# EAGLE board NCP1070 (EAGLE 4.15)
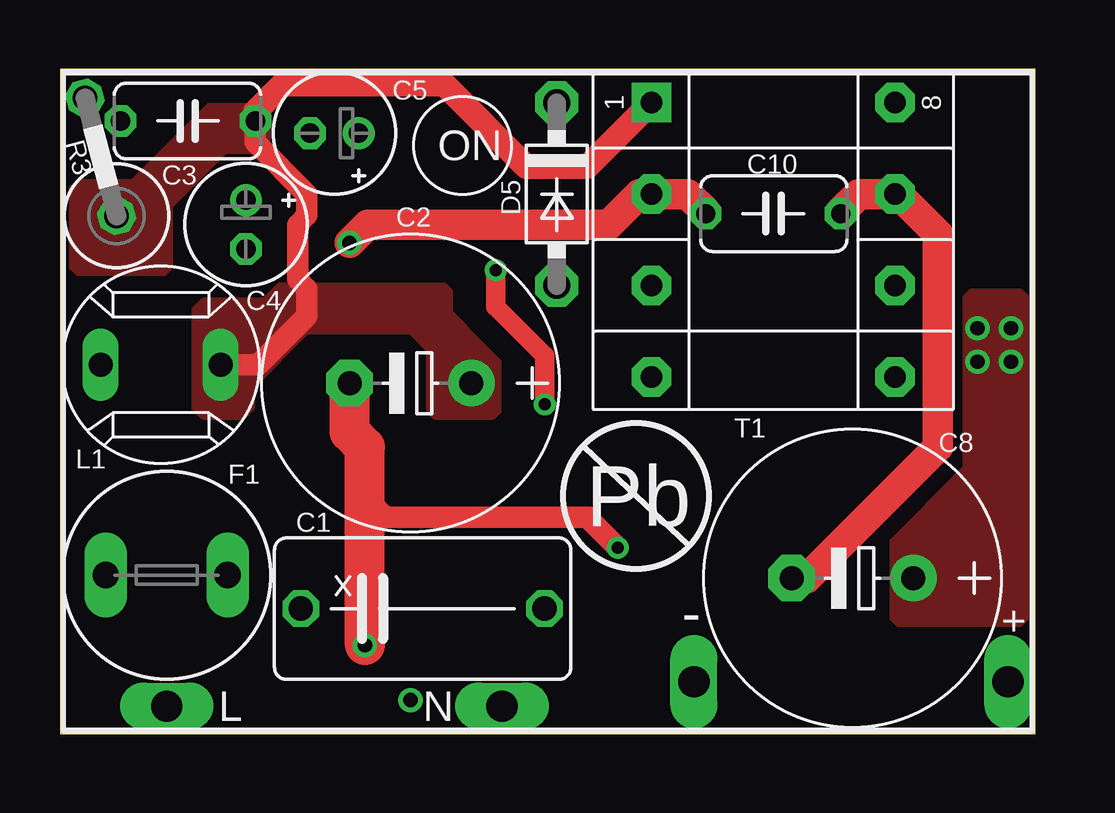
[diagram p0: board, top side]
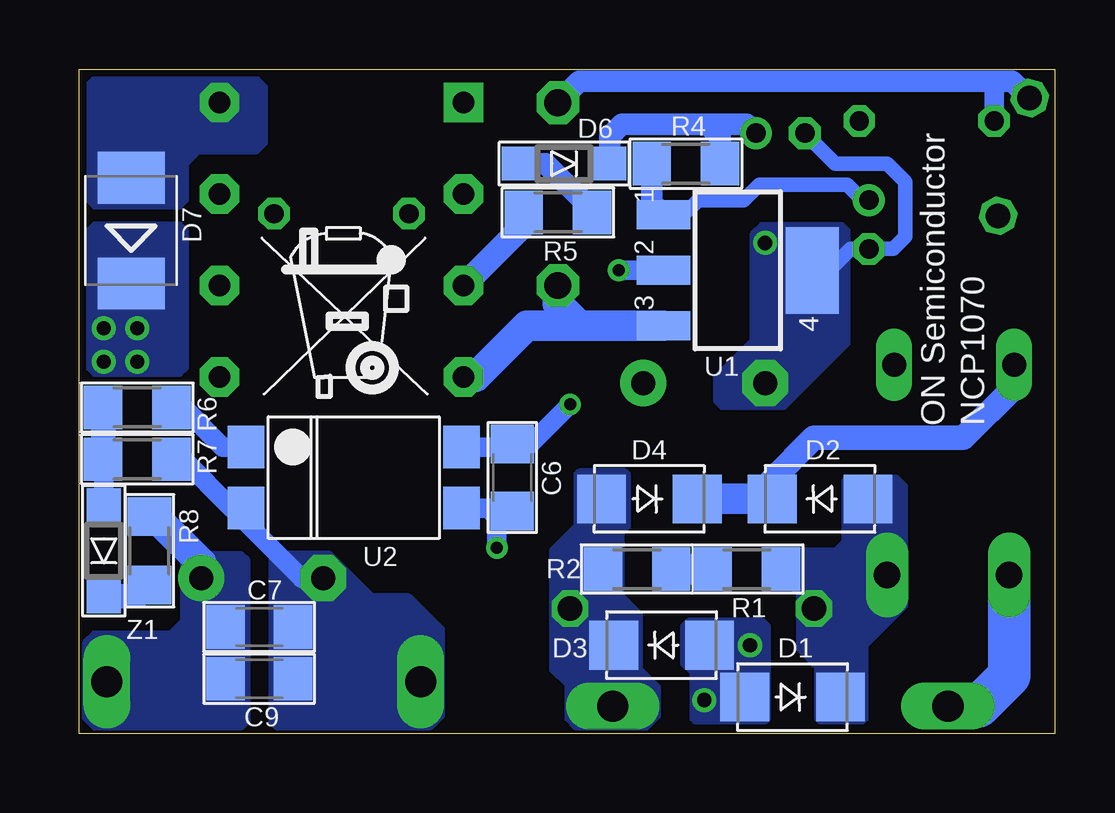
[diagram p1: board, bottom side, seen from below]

Size 40.64 x 27.69 mm. Coordinates in mm from the lower left corner, seen from the top.
Outline: 0,0 40.64,0 40.64,27.69 0,27.69 0,0
Copper layers (1*16): Top 0.035mm / dielectric 1.5mm / Bottom 0.035mm
Design rules "default": minimum track width 10mil, minimum drill 10mil, track to track 8mil, track to pad 8mil, pad to pad 8mil, via to via 8mil, smd to smd 8mil, copper to edge 5mil, drill to drill 8mil, minimum pad ring 10mil, minimum via ring 8mil, stop-mask expansion 4mil, vias tented up to drill 0mil, thermal gap 10mil

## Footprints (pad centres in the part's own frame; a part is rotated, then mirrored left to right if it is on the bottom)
1-PIN = drill 1.3 long: P$1 0,0
XC12.5X6MM-LS10.16 = drill 1.016 octagon: 1 -5.08,0; 2 5.08,0
E5-12,5 = drill 1 pad 1.93 round: + -2.54,0 | drill 1 pad 1.93 octagon: - 2.54,0
C043-0316X0624 = drill 0.8 pad 1.27 octagon: P$1 -2.81,0; P$2 2.81,0
E2-5 = drill 0.813 pad 1.27 round: + -1.016,0 | drill 0.813 pad 1.27 octagon: - 1.016,0
C1206 = smd 1.6 x 1.8: 1 -1.4,0; 2 1.4,0
SMA-DIODE = smd 2.032 x 2.032: A 1.994,0; C -1.994,0
DO41-7 = drill 1.118 pad 1.778 octagon: A 3.81,0; C -3.81,0
SOD123 = smd 1.4 x 1.4: A 1.9,0; C -1.9,0
SMB = smd 2.159 x 2.794: A 2.2,0; C -2.2,0
TR5 = drill 1.1 pad 1.778 long: 1 -2.54,0; 2 2.54,0
WE-7447728102 = drill 1 long: P$1 -2.5,0; P$2 2.5,0
R1206 = smd 1.6 x 1.803: 1 -1.422,0; 2 1.422,0
0414V = drill 1.016 octagon: 1 -2.54,0; 2 2.54,0
EE13/6/6 = drill 0.9 pad 1.651 square: 1 -5.715,-5.076 | drill 0.9 pad 1.651 octagon: 2 -1.905,-5.076; 3 1.905,-5.076; 4 5.715,-5.076; 5 5.715,5.076; 6 1.905,5.076; 7 -1.905,5.076; 8 -5.715,5.076
SOT-223 = smd 1.219 x 2.235: 1 -2.311,-3.099; 2 0,-3.099; 3 2.311,-3.099 | smd 3.6 x 2.2: 4 0,3.099
4PIN-SURFMOUNT-OPTO = smd 1.524 x 1.778: 1 4.496,-1.27; 2 4.496,1.27; 3 -4.496,1.27; 4 -4.496,-1.27

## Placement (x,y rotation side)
+  1_PIN-CONN1-PIN  [1-PIN]  39.5,2.16 0 top
-  1_PIN-CONN1-PIN  [1-PIN]  26.42,2.16 0 top
C1  100nF  [XC12.5X6MM-LS10.16]  15.11,5.21 0 top
C2  10uF  [E5-12,5]  14.61,14.61 180 top
C3  1nF  [C043-0316X0624]  5.33,25.53 180 top
C4  22uF  [E2-5]  7.75,21.21 270 top
C5  4.7uF  [E2-5]  11.43,25.02 180 top
C6  1nF  [C1206]  22.61,10.67 90 bottom
C7  0.1uF  [C1206]  33.15,4.45 0 bottom
C8  1200uF  [E5-12,5]  33.02,6.48 180 top
C9  0.1uF  [C1206]  33.15,2.29 0 bottom
C10  1nF  [C043-0316X0624]  29.72,21.67 0 top
D1  MRA4007  [SMA-DIODE]  10.92,1.52 180 bottom
D2  MRA4007  [SMA-DIODE]  9.78,9.78 0 bottom
D3  MRA4007  [SMA-DIODE]  16.38,3.68 0 bottom
D4  MRA4007  [SMA-DIODE]  16.89,9.78 180 bottom
D5  1N4937  [DO41-7]  20.7,22.48 270 top
D6  MMSD4148A  [SOD123]  20.45,23.75 180 bottom
D7  MBRS260T3  [SMB]  38.48,20.96 90 bottom
F1  1.5A  [TR5]  4.45,6.6 0 top
L  1_PIN-CONN1-PIN  [1-PIN]  4.45,1.14 270 top
L1  1mH,500mA  [WE-7447728102]  4.19,15.37 0 top
N  1_PIN-CONN1-PIN  [1-PIN]  18.42,1.14 270 top
R1  3.3M  [R1206]  12.83,6.86 0 bottom
R2  3.3M  [R1206]  17.4,6.86 0 bottom
R3  68K  [0414V]  1.7,24.03 105 top
R4  1K  [R1206]  15.37,23.75 0 bottom
R5  10  [R1206]  20.7,21.72 180 bottom
R6  33  [R1206]  38.23,13.59 0 bottom
R7  680  [R1206]  38.23,11.43 0 bottom
R8  240  [R1206]  37.72,7.62 270 bottom
T1  [EE13/6/6]  29.72,20.57 270 top
U1  NCP1075  [SOT-223]  13.21,19.3 270 bottom
U2  PS2561L_1  [4PIN-SURFMOUNT-OPTO]  29.21,10.67 180 bottom
U$1  [ON-SEMI-0.18"]  16.76,24.51 0 top
U$3  [WEEE_SMALL]  29.44,15.34 0 bottom
Z1  MMSZ5229B  [SOD123]  39.62,7.62 90 bottom

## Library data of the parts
+ - L N = My CONNECTOR lib
C1-C10 R1-R8 = rcl
D1-D7 Z1 = diode
F1 = fuse
L1 = MY  INDUCTOR Lib
T1 = My X-former
U1 = My IC Lib
U2 = optocoupler
U$1 U$3 = My Sign Lib

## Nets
N$1: C1.1 D1.C D2.A F1.2 R1.2
N$2: F1.1 L.P$1
N$3: C2.+ C3.P$1 L1.P$2 R3.1 T1.1
N$4: C1.2 D3.C D4.A N.P$1 R2.1
N$5: R1.1 R2.2
N$6: C2.- C4.- C5.- C6.1 C10.P$1 D1.A D3.A T1.2 U1.4 U2.3
N$7: R5.2 T1.3
N$8: C4.+ R4.1 U1.1
N$9: D6.A R5.1
N$10: D2.C D4.C L1.P$1
N$11: C5.+ D6.C R4.2
N$12: D5.A T1.4 U1.3
N$13: C3.P$2 D5.C R3.2
N$14: R6.2 U2.1
N$15: C6.2 U1.2 U2.4
N$16: +.P$1 C7.1 C8.+ C9.1 D7.C R8.1
N$17: D7.A T1.8
N$18: -.P$1 C7.2 C8.- C9.2 C10.P$2 R7.2 T1.7 U2.2
N$19: R6.1 R7.1 Z1.A
N$20: R8.2 Z1.C

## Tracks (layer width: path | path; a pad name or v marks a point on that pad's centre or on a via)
N$1
  pour Bottom (no thermals): 6.6,10.67 8.64,10.67 8.76,10.54 8.76,8 9.14,7.62 11.94,7.62 12.07,7.49 12.07,6.22 11.94,6.1 10.92,6.1 10.67,5.84 10.67,3.56 9.91,2.79 9.91,0.64 9.78,0.51 8,0.51 7.87,0.64 7.87,3.68 6.22,5.33 6.22,10.29
N$2
  Bottom 1.778: L.P$1 3.18,1.14 1.91,2.41 F1.1
N$3
  Top 0.889: L1.P$2 6.69,15.45 6.73,15.49 6.86,15.37 8.26,15.37 10.29,17.4 10.29,18.54 9.91,18.92 9.91,21.21 10.29,21.59 10.29,22.48 8.13,24.64 8.13,25.53
  Top 1.016: C3.P$1 8.13,25.53 8.13,25.91 9.27,27.05 16,27.05 19.43,23.62 21.97,23.62 T1.1
  pour Top (isolate 1.016, no thermals): 5.59,17.65 5.59,13.59 5.97,13.21 7.62,13.21 8,13.59 8,14.48 10.29,16.76 14.61,16.76 15.37,16 15.37,13.46 15.62,13.21 18.03,13.21 18.29,13.46 18.29,15.49 16.26,17.53 16.26,18.42 16,18.67 9.14,18.67 8.51,18.03 5.97,18.03
  pour Top (isolate 0.254, no thermals): 0.51,19.43 0.51,22.73 0.76,22.99 3.05,22.99 6.22,26.16 8.38,26.16 8.64,25.91 8.64,24.51 8.38,24.26 6.86,24.26 4.57,21.97 4.57,19.43 4.32,19.18 0.76,19.18
N$4
  pour Bottom (no thermals): 16.51,0.76 16.51,1.91 17.27,2.67 17.27,4.95 18.03,5.72 18.03,8.38 17.78,8.64 17.78,10.8 17.91,10.92 19.81,10.92 19.94,10.8 19.94,8.64 20.96,7.62 20.96,2.67 20.32,2.03 20.32,0.64 19.94,0.25 17.02,0.25
N$5
  Bottom 1.27: 16,6.86 R2.2 R1.1
N$6  (via drill 0.5, 0.6)
  Top 0.889: 12.7,9.4 13.21,9.4 13.59,9.02 22.1,9.02 22.1,8.89 v23.24,7.75
  Top 1.27: v12.07,20.45 12.83,21.21 22.86,21.21 24.13,22.48 T1.2 26.16,22.48 26.92,21.72 26.91,21.7 C10.P$1
  Top 1.676: v12.7,3.68 12.7,9.4 12.7,11.94 12.07,12.57 C2.-
  Bottom 0.61: C5.- 9.14,23.75 6.99,23.75 6.22,22.99 6.22,20.7 6.73,20.19 C4.- 8.51,20.19 9.4,19.3 U1.4 10.16,19.3
  Bottom 0.813: C6.1 22.73,9.4 23.62,9.4 | 23.62,9.4 U2.3 | v23.24,7.75 23.24,9.02 23.62,9.4
  other vias: 14.61,1.4
  pour Bottom (no thermals): 15.49,4.45 15.49,2.92 15.11,2.54 15.11,0.64 14.99,0.51 12.07,0.51 11.94,0.64 11.94,4.45 12.19,4.7 15.24,4.7
  pour Bottom (isolate 0.254, no thermals): 8.64,20.96 8.64,16.26 11.3,13.59 13.84,13.59 14.1,13.84 14.1,14.86 12.57,16.38 12.57,20.83 12.19,21.21 8.89,21.21
N$7
  Bottom 1.016: R5.2 22.1,21.72 22.1,21.21 T1.3
N$8
  Bottom 0.61: U1.1 15.47,21.62 14.86,22.23 12.95,22.23 12.32,22.86 8.64,22.86 8,22.23 C4.+
  Bottom 0.889: 16.28,21.62 16.26,21.59 | U1.1 16.28,21.62 | R4.1 16.79,22.12 16.28,21.62
N$9
  Bottom 0.889: R5.1 19.28,21.82 21.21,23.75 D6.A 22.23,23.75
N$10
  Bottom 1.016: L1.P$1 1.69,14.44 3.81,12.32 10.03,12.32 11.81,10.54 11.81,9.91 11.77,9.87 D2.C
  Bottom 1.27: D2.C D4.C
N$11
  Bottom 0.889: D6.C 18.55,24.89 18.03,25.4 14.48,25.4 | 14.48,25.4 12.83,25.4 C5.+ | R4.2 13.95,24.87 14.48,25.4
N$12
  Bottom 1.27: U1.3 19.81,16.99 | 19.81,16.99 22,16.99 24.13,14.86 T1.4 | 19.81,16.99 19.81,17.02 20.7,17.91 D5.A
N$13
  Bottom 0.813: C3.P$2 2.52,27.16 2.54,27.18
  Bottom 0.889: R3.2 1.08,26.48 1.78,27.18 2.54,27.18 19.81,27.18 D5.C
N$14
  Bottom 0.813: 36.83,13.59 R6.2 36.32,13.59 34.67,11.94 U2.1
N$15  (via drill 0.5)
  Top 0.813: v20.19,13.72 20.19,15.75 18.16,17.78 v18.16,19.3
  Bottom 0.813: v18.16,19.3 U1.2 | U2.4 22.73,11.94 C6.2 21.84,12.07 v20.19,13.72
N$16  (via drill 0.6)
  Bottom 1.27: R8.1 37.49,9.04 35.56,7.11 C8.+
  other vias: 38.23,16.89 39.62,16.89 38.23,15.49 39.62,15.49
  pour Top (no thermals): 37.72,18.16 37.72,11.05 37.59,10.92 34.67,8 34.67,4.83 34.93,4.57 40.01,4.57 40.26,4.83 40.26,18.16 40.01,18.42 37.97,18.42
  pour Bottom (no thermals): 36.2,15.24 36.2,20.96 36.45,21.21 40.01,21.21 40.26,20.96 40.26,15.24 40.01,14.99 36.45,14.99
  pour Bottom (no thermals): 33.66,7.24 33.66,0.51 33.91,0.25 40.01,0.25 40.39,0.64 40.39,3.81 40.01,4.19 36.83,4.19 36.32,4.7 36.32,7.11 35.94,7.49 33.91,7.49
N$17
  pour Bottom (isolate 0.305, no thermals): 33.27,27.31 40.01,27.31 40.26,27.05 40.26,22.23 40.01,21.97 36.45,21.97 36.2,22.23 36.2,23.75 35.69,24.26 33.27,24.26 32.89,24.64 32.89,26.92
N$18
  Top 1.27: C8.- 31.12,6.48 36.58,11.94 36.58,20.83 34.93,22.48 T1.7 33.27,22.48 32.51,21.72 32.53,21.7 C10.P$2
  Bottom 0.813: 30.35,6.48 C8.- 31.37,6.48 33.71,8.81 U2.2 34.29,9.4 36.32,11.43 R7.2
  pour Bottom (no thermals): 30.23,7.49 32.51,7.49 32.64,7.37 32.64,0.51 32.39,0.25 26.04,0.25 25.53,0.76 25.53,4.32 26.92,5.72 28.45,5.72
N$19
  Bottom 0.813: R7.1 39.62,11.43 Z1.A
  Bottom 1.016: R7.1 R6.1
N$20
  Bottom 1.016: R8.2 37.72,6.22 38.22,5.72 Z1.C

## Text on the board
tPlace: Pb
bPlace: NCP1070 | ON Semiconductor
